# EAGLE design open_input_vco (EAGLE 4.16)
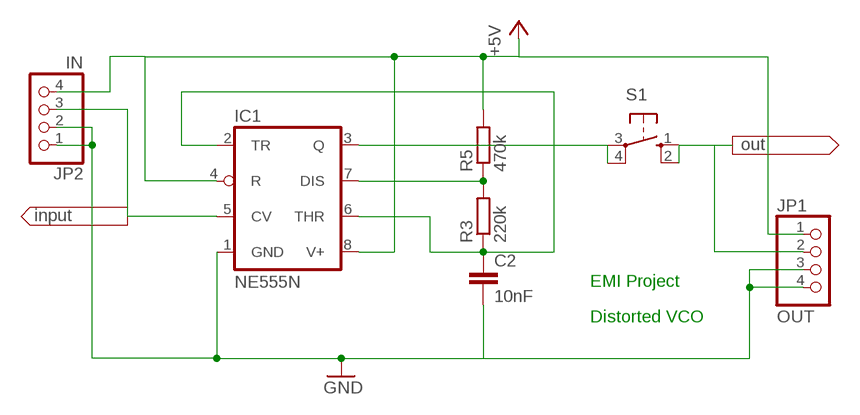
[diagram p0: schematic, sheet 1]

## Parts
C2  10nF  C-EU025-024X044  [C025-024X044]
IC1  NE555N  [DIL08]
JP1  OUT  PINHD-1X4  [1X04]
JP2  IN  PINHD-1X4  [1X04]
R3  220k  R-EU_0207/7  [0207/7]
R5  470k  R-EU_0207/7  [0207/7]
S1  10-XX  [B3F-10XX]

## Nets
+5V: IC1.4(R) IC1.8(V+) JP1.1 JP2.4 R5.2
GND: C2.2 IC1.1(GND) JP1.3 JP1.4 JP2.1 JP2.2
N$2: C2.1 IC1.2(TR) IC1.6(THR) R3.1
N$3: JP1.2 S1.1(S) S1.2(S1)
N$4: IC1.3(Q) S1.3(P) S1.4(P1)
N$5: IC1.5(CV) JP2.3
N$6: IC1.7(DIS) R3.2 R5.1

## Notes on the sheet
- EMI Project
- Distorted VCO

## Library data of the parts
C2 = rcl:C-EU: CAPACITOR, European symbol
IC1 = linear:*555: TIMER
JP1 JP2 = pinhead:PINHD-1X4: PIN HEADER
R3 R5 = rcl:R-EU_: RESISTOR, European symbol
S1 = switch-omron:10-XX: OMRON SWITCH

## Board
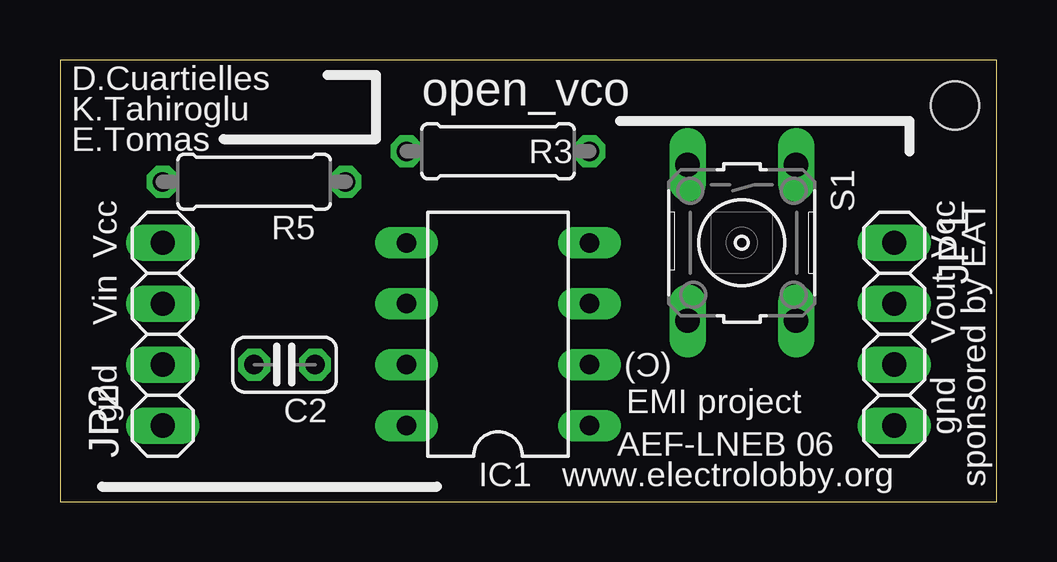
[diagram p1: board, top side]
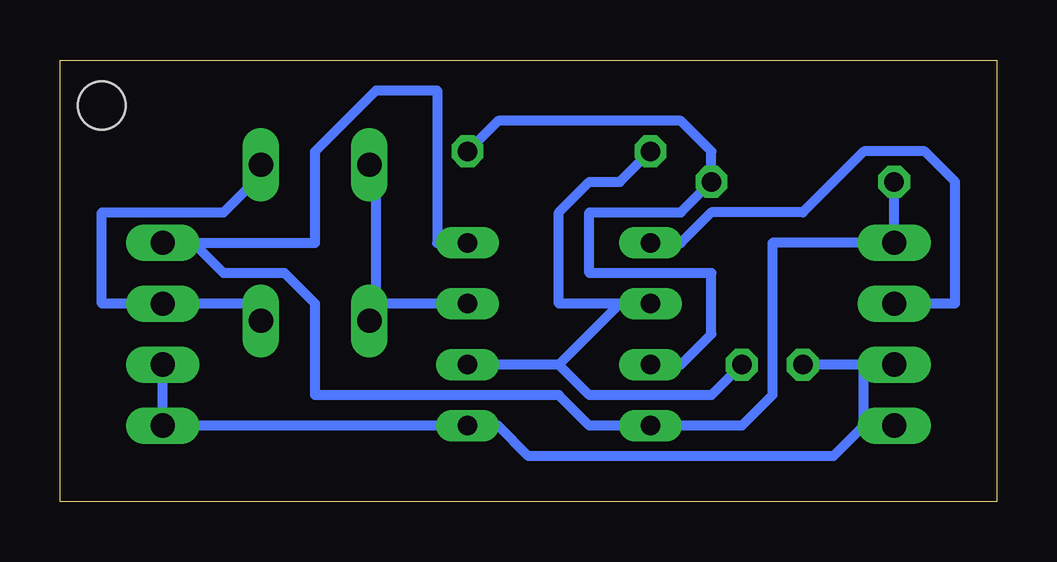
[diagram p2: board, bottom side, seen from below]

Size 39.04 x 18.4 mm. Coordinates in mm from the lower left corner, seen from the top.
Outline: 0,0 39.04,0 39.04,18.4 0,18.4 0,0
Copper layers (1*16): Top 0.035mm / dielectric 1.5mm / Bottom 0.035mm
Design rules "default": minimum track width 10mil, minimum drill 24mil, track to track 8mil, track to pad 8mil, pad to pad 8mil, via to via 8mil, smd to smd 8mil, copper to edge 40mil, drill to drill 8mil, minimum pad ring 10mil, minimum via ring 8mil, stop-mask expansion 4mil, vias tented up to drill 0mil, thermal gap 10mil
Holes 2 mm at 37.3,16.5

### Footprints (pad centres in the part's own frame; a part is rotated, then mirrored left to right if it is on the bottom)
C025-024X044 = drill 0.813 octagon: 1 -1.27,0; 2 1.27,0
DIL08 = drill 0.813 long: 1 -3.81,-3.81; 2 -1.27,-3.81; 3 1.27,-3.81; 4 3.81,-3.81; 5 3.81,3.81; 6 1.27,3.81; 7 -1.27,3.81; 8 -3.81,3.81
1X04 = drill 1.016 long: 1 -3.81,0; 2 -1.27,0; 3 1.27,0; 4 3.81,0
0207/7 = drill 0.813 octagon: 1 -3.81,0; 2 3.81,0
B3F-10XX = drill 1.016 long: 1 -3.251,2.261; 2 3.251,2.261; 3 -3.251,-2.261; 4 3.251,-2.261

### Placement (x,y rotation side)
C2  9.36,5.71 180 top
IC1  18.25,6.98 90 top
JP1  34.76,6.98 270 top
JP2  4.28,6.98 90 top
R3  18.25,14.6 0 top
R5  8.09,13.33 180 top
S1  28.41,10.79 270 top

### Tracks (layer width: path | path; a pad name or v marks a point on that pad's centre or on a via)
+5V
  Bottom 0.406: 33.49,10.79 28.41,10.79 28.41,14.6 25.87,17.14 23.33,17.14 23.33,10.79 IC1.4 | R5.2 JP2.4 9.36,10.79 9.36,4.44 10.63,3.17 IC1.8 16.98,3.17 18.25,4.44 28.41,4.44 28.41,8.25 29.68,9.52 32.22,9.52 33.49,10.79 | 33.49,10.79 JP1.1
GND
  Bottom 0.254: 20.79,3.17 IC1.1
  Bottom 0.406: 5.55,5.71 C2.2 | 5.55,3.17 5.55,5.71 | 5.55,5.71 JP2.2 | IC1.1 JP1.4 JP1.3 | 5.55,3.17 6.82,1.9 19.52,1.9 20.79,3.17 | JP2.1 5.55,3.17
N$2
  Bottom 0.406: C2.1 11.9,4.44 16.98,4.44 18.25,5.71 | 18.25,5.71 IC1.2 | 18.25,5.71 15.71,8.25 | R3.1 15.71,13.33 16.98,13.33 18.25,12.06 18.25,8.25 15.71,8.25 | 15.71,8.25 IC1.6
N$3
  Bottom 0.406: S1.2 30.95,8.25 JP1.2 37.3,8.25 37.3,12.06 32.22,12.06 30.95,13.33 S1.1
N$4
  Bottom 0.406: IC1.3 25.87,8.25 | 25.87,8.25 25.87,13.33 S1.3 | 25.87,8.25 S1.4
N$5
  Bottom 0.406: IC1.5 13.17,10.79 11.9,12.06 8.09,12.06 5.55,14.6 3.01,14.6 1.74,13.33 1.74,8.25 JP2.3
N$6
  Bottom 0.406: IC1.7 13.17,5.71 11.9,6.98 11.9,9.52 16.98,9.52 16.98,12.06 13.17,12.06 R5.1 11.9,14.6 13.17,15.87 20.79,15.87 R3.2

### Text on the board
tPlace: D.Cuartielles | open_vco | K.Tahiroglu | E.Tomas | Vcc | Vcc | Vin | Vout | (C) | EMI project | gnd | gnd | AEF-LNEB 06 | www.electrolobby.org | sponsored by EAT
